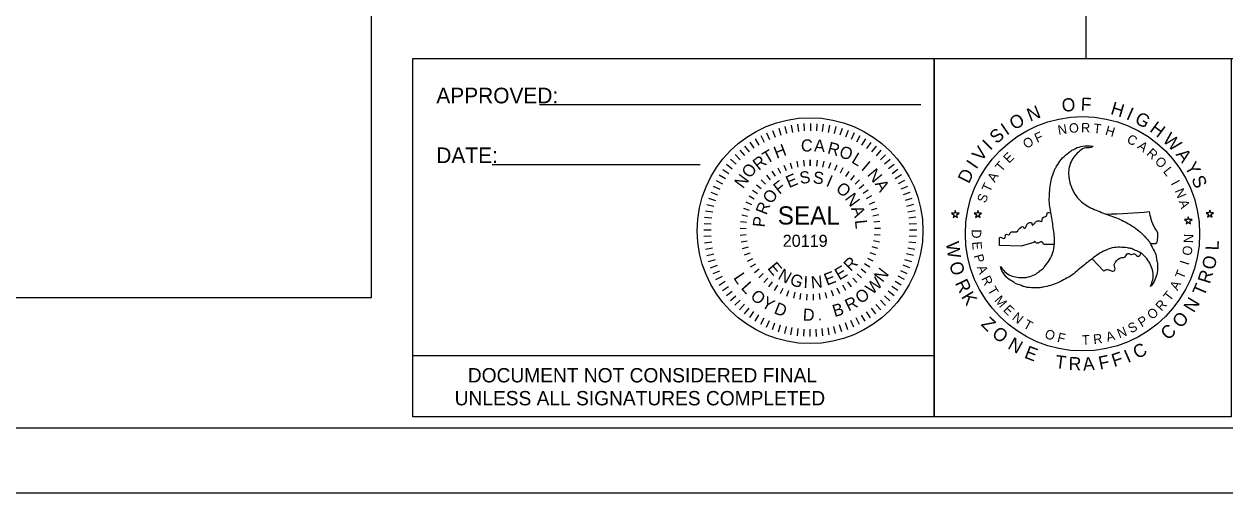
# Model space of a CAD drawing. Extents: x 1615234 to 1620694, y 898143 to 902846.
# Drawn here: x 1618110 to 1619493, y 899546 to 900086 of the extents above; entities that cross this region are included whole.
import ezdxf

# ---------------------------------------------------------------- set-up
doc = ezdxf.new("R2010")
doc.units = 0
for name, color, linetype in [('Default', 7, 'Continuous'), ('DEV BORDER CELL', 7, 'Continuous'), ('DEV DOT SWIRL SEAL CELL', 7, 'Continuous'), ('Scratch_Level_0', 7, 'Continuous'), ('Sheet Plan CELL', 7, 'Continuous'), ('Sheet Plot Border Outside CELL', 7, 'Continuous'), ('Sheet Sticker Exception Certification CELL', 7, 'Continuous'), ('Text', 7, 'Continuous')]:
    doc.layers.add(name, color=color, linetype=linetype)

msp = doc.modelspace()

# ---------------------------------------------------------------- linework, layer by layer
at = {"layer": 'Default'}
for p, q in [((1618971.7, 899963.7), (1618974.6, 899955.8)), ((1618978.7, 899966.1), (1618981.1, 899958.1)), ((1618985.8, 899968), (1618987.8, 899959.9)), ((1618993.1, 899969.6), (1618994.6, 899961.4)), ((1619000.4, 899970.7), (1619001.4, 899962.4)), ((1619007.8, 899971.4), (1619008.2, 899963)), ((1619015.2, 899971.6), (1619015.2, 899963.2)), ((1619022.6, 899971.3), (1619022.1, 899963)), ((1619029.9, 899970.7), (1619028.9, 899962.4)), ((1619037.3, 899969.6), (1619035.8, 899961.3)), ((1619044.5, 899968), (1619042.5, 899959.9)), ((1619051.6, 899966), (1619049.2, 899958)), ((1619058.6, 899963.6), (1619055.7, 899955.8)), ((1618945.5, 899949.9), (1618950.2, 899943.1)), ((1618951.7, 899953.9), (1618956, 899946.8)), ((1618958.2, 899957.6), (1618962, 899950.2)), ((1618964.8, 899960.8), (1618968.2, 899953.2)), ((1619065.5, 899960.7), (1619062, 899953.1)), ((1619072.1, 899957.5), (1619068.2, 899950.1)), ((1619078.6, 899953.8), (1619074.2, 899946.7)), ((1619084.8, 899949.8), (1619080, 899942.9)), ((1618928.4, 899935.7), (1618934.3, 899929.8)), ((1618933.8, 899940.8), (1618939.4, 899934.6)), ((1618939.5, 899945.6), (1618944.7, 899939)), ((1619090.8, 899945.4), (1619085.6, 899938.8)), ((1619096.5, 899940.7), (1619090.9, 899934.4)), ((1619101.8, 899935.6), (1619095.9, 899929.7)), ((1618918.6, 899924.7), (1618925.2, 899919.5)), ((1618923.3, 899930.4), (1618929.6, 899924.8)), ((1618977.6, 899920.5), (1618980.8, 899914.4)), ((1618984.6, 899923.8), (1618987.3, 899917.4)), ((1618992, 899926.4), (1618994, 899919.7)), ((1618999.6, 899928.3), (1619000.9, 899921.4)), ((1619007.3, 899929.4), (1619008, 899922.5)), ((1619015.1, 899929.8), (1619015.1, 899922.8)), ((1619015.1, 899922.8), (1619015.1, 899929.8)), ((1619022.9, 899929.4), (1619022.2, 899922.5)), ((1619030.6, 899928.2), (1619029.3, 899921.4)), ((1619038.2, 899926.4), (1619036.2, 899919.7)), ((1619045.6, 899923.8), (1619043, 899917.3)), ((1619052.7, 899920.5), (1619049.4, 899914.3)), ((1619106.9, 899930.2), (1619100.6, 899924.6)), ((1619111.6, 899924.5), (1619105.1, 899919.3)), ((1618910.2, 899912.5), (1618917.3, 899908.2)), ((1618914.2, 899918.7), (1618921.1, 899913.9)), ((1618958.6, 899906.8), (1618963.5, 899901.8)), ((1618964.5, 899912), (1618968.9, 899906.6)), ((1618970.8, 899916.6), (1618974.6, 899910.8)), ((1619059.4, 899916.5), (1619055.6, 899910.7)), ((1619065.7, 899911.9), (1619061.3, 899906.5)), ((1619071.6, 899906.7), (1619066.7, 899901.7)), ((1619116, 899918.5), (1619109.2, 899913.8)), ((1619120, 899912.3), (1619112.9, 899908)), ((1618903.3, 899899.4), (1618910.9, 899895.9)), ((1618906.5, 899906), (1618913.9, 899902.1)), ((1618948.6, 899894.9), (1618954.3, 899891)), ((1618953.3, 899901.1), (1618958.6, 899896.6)), ((1619076.9, 899901), (1619071.5, 899896.5)), ((1619081.6, 899894.8), (1619075.9, 899890.8)), ((1619123.7, 899905.8), (1619116.3, 899902)), ((1619126.9, 899899.2), (1619119.3, 899895.8)), ((1618898, 899885.5), (1618906, 899883.1)), ((1618900.4, 899892.5), (1618908.2, 899889.6)), ((1618941, 899881.3), (1618947.4, 899878.5)), ((1618944.5, 899888.3), (1618950.5, 899884.9)), ((1619085.7, 899888.2), (1619079.6, 899884.8)), ((1619089.2, 899881.2), (1619082.8, 899878.4)), ((1619129.8, 899892.3), (1619121.9, 899889.4)), ((1619132.2, 899885.3), (1619124.2, 899882.9)), ((1618894.4, 899871.2), (1618902.7, 899869.7)), ((1618896, 899878.4), (1618904.1, 899876.4)), ((1618936.1, 899866.5), (1618942.9, 899865)), ((1618938.2, 899874), (1618944.8, 899871.8)), ((1619091.9, 899873.8), (1619085.3, 899871.7)), ((1619094, 899866.3), (1619087.2, 899864.8)), ((1619134.1, 899878.2), (1619126, 899876.2)), ((1619135.7, 899870.9), (1619127.5, 899869.4)), ((1618892.7, 899856.5), (1618901, 899856)), ((1618893.3, 899863.8), (1618901.6, 899862.8)), ((1618934.8, 899858.8), (1618941.7, 899857.9)), ((1619095.3, 899858.6), (1619088.4, 899857.8)), ((1619136.8, 899863.6), (1619128.5, 899862.6)), ((1619137.5, 899856.2), (1619129.1, 899855.8)), ((1618892.4, 899849.1), (1618900.8, 899849.1)), ((1618892.6, 899841.7), (1618901, 899842.1)), ((1618934.2, 899851), (1618941.2, 899850.8)), ((1618934.4, 899843.2), (1618941.4, 899843.7)), ((1619095.7, 899843), (1619088.7, 899843.5)), ((1619095.9, 899850.8), (1619088.9, 899850.7)), ((1619137.4, 899841.4), (1619129.1, 899841.9)), ((1619137.7, 899848.8), (1619129.3, 899848.8)), ((1618893.3, 899834.3), (1618901.6, 899835.3)), ((1618894.4, 899827), (1618902.6, 899828.5)), ((1618935.4, 899835.4), (1618942.2, 899836.6)), ((1618937, 899827.8), (1618943.8, 899829.6)), ((1619093, 899827.6), (1619086.3, 899829.5)), ((1619087.9, 899836.7), (1619094.7, 899835.5)), ((1619135.6, 899826.7), (1619127.4, 899828.2)), ((1619136.8, 899834.1), (1619128.5, 899835.1)), ((1618896, 899819.7), (1618904.1, 899821.7)), ((1618897.9, 899812.6), (1618905.9, 899815)), ((1618939.5, 899820.4), (1618946, 899822.8)), ((1618942.6, 899813.2), (1618948.8, 899816.3)), ((1618946.3, 899806.4), (1618952.3, 899810)), ((1619083.7, 899806.2), (1619077.7, 899809.9)), ((1619087.5, 899813.1), (1619081.2, 899816.2)), ((1619090.6, 899820.2), (1619084.1, 899822.7)), ((1619132.1, 899812.4), (1619124.1, 899814.8)), ((1619134.1, 899819.5), (1619126, 899821.5)), ((1618900.3, 899805.6), (1618908.2, 899808.5)), ((1618903.2, 899798.7), (1618910.8, 899802.1)), ((1618906.4, 899792.1), (1618913.8, 899795.9)), ((1618950.8, 899799.9), (1618956.3, 899804.2)), ((1618955.8, 899794), (1618960.9, 899798.7)), ((1619074.2, 899793.9), (1619069.1, 899798.6)), ((1619079.2, 899799.8), (1619073.7, 899804)), ((1619126.8, 899798.5), (1619119.2, 899802)), ((1619129.7, 899805.4), (1619121.9, 899808.3)), ((1618910, 899785.6), (1618917.2, 899789.9)), ((1618914.1, 899779.4), (1618920.9, 899784.1)), ((1618961.4, 899788.5), (1618966, 899793.7)), ((1618967.5, 899783.6), (1618971.6, 899789.2)), ((1618974, 899779.3), (1618977.6, 899785.3)), ((1618980.9, 899775.7), (1618983.9, 899782)), ((1619049, 899775.6), (1619046.1, 899782)), ((1619056, 899779.2), (1619052.4, 899785.3)), ((1619062.5, 899783.5), (1619058.4, 899789.2)), ((1619068.6, 899788.4), (1619064, 899793.6)), ((1619115.9, 899779.2), (1619109, 899783.9)), ((1619119.9, 899785.4), (1619112.8, 899789.7)), ((1619123.6, 899791.9), (1619116.2, 899795.8)), ((1618918.4, 899773.4), (1618925, 899778.6)), ((1618923.2, 899767.7), (1618929.4, 899773.3)), ((1618928.3, 899762.3), (1618934.2, 899768.2)), ((1618988.2, 899772.7), (1618990.5, 899779.3)), ((1618997.3, 899777.3), (1618995.6, 899770.5)), ((1619003.3, 899769), (1619004.3, 899775.9)), ((1619011.1, 899768.2), (1619011.4, 899775.2)), ((1619018.9, 899768.2), (1619018.6, 899775.2)), ((1619026.6, 899769), (1619025.7, 899775.9)), ((1619034.3, 899770.5), (1619032.6, 899777.2)), ((1619041.8, 899772.7), (1619039.5, 899779.3)), ((1619106.8, 899767.5), (1619100.5, 899773.1)), ((1619111.5, 899773.2), (1619104.9, 899778.4)), ((1618933.6, 899757.2), (1618939.2, 899763.5)), ((1618939.3, 899752.5), (1618944.5, 899759.1)), ((1618945.3, 899748.1), (1618950, 899755)), ((1619084.6, 899748), (1619079.9, 899754.8)), ((1619090.6, 899752.3), (1619085.4, 899758.9)), ((1619096.3, 899757.1), (1619090.7, 899763.3)), ((1619101.7, 899762.2), (1619095.8, 899768.1)), ((1618951.5, 899744.1), (1618955.8, 899751.2)), ((1618958, 899740.4), (1618961.9, 899747.8)), ((1618964.6, 899737.2), (1618968, 899744.8)), ((1618971.5, 899734.3), (1618974.4, 899742.1)), ((1619058.4, 899734.2), (1619055.5, 899742.1)), ((1619065.3, 899737.1), (1619061.9, 899744.7)), ((1619071.9, 899740.3), (1619068.1, 899747.7)), ((1619078.4, 899743.9), (1619074.1, 899751.1)), ((1618978.5, 899731.9), (1618980.9, 899739.9)), ((1618985.6, 899729.9), (1618987.6, 899738)), ((1618992.8, 899728.3), (1618994.3, 899736.6)), ((1619000.2, 899727.2), (1619001.2, 899735.5)), ((1619007.5, 899726.6), (1619008, 899734.9)), ((1619014.9, 899726.3), (1619014.9, 899734.7)), ((1619022.3, 899726.5), (1619021.8, 899734.9)), ((1619029.7, 899727.2), (1619028.7, 899735.5)), ((1619037, 899728.3), (1619035.5, 899736.5)), ((1619044.3, 899729.9), (1619042.3, 899738)), ((1619051.4, 899731.8), (1619048.9, 899739.8))]:
    msp.add_line(p, q, dxfattribs=at)
at = {"layer": 'DEV BORDER CELL'}
for p, q in [((1618703.2, 899993.5), (1619142.2, 899993.5)), ((1619157.6, 899976), (1619157.6, 899634)), ((1618648.8, 899924.2), (1618888.2, 899924.2))]:
    msp.add_line(p, q, dxfattribs=at)
for points in [[(1620223.1, 902771.2), (1615723.1, 902771.2), (1615723.1, 899621.2), (1620223.1, 899621.2)], [(1618557.5, 900046.5), (1619157.6, 900046.5), (1619157.6, 899634), (1618557.5, 899634)], [(1619157.6, 900046.5), (1619499.6, 900046.5), (1619499.6, 899634), (1619157.6, 899634)]]:
    msp.add_lwpolyline(points, close=True, dxfattribs=at)
msp.add_circle((1619014.8, 899848.2), 130, dxfattribs=at)
at = {"layer": 'DEV DOT SWIRL SEAL CELL'}
for p, q in [((1619177.8, 899868.5), (1619180.5, 899866.6)), ((1619181.1, 899868.5), (1619177.8, 899868.5)), ((1619180.5, 899866.6), (1619179.5, 899863.4)), ((1619179.5, 899863.4), (1619182, 899865.4)), ((1619182, 899871.5), (1619181.1, 899868.5)), ((1619183.1, 899868.5), (1619182, 899871.5)), ((1619182, 899865.4), (1619184.7, 899863.4)), ((1619182, 899865.4), (1619184.7, 899863.4)), ((1619186.4, 899868.5), (1619183.1, 899868.5)), ((1619183.7, 899866.6), (1619186.4, 899868.5)), ((1619183.7, 899866.6), (1619186.4, 899868.5)), ((1619184.7, 899863.4), (1619183.7, 899866.6)), ((1619184.7, 899863.4), (1619183.7, 899866.6)), ((1619207.1, 899868.5), (1619203.8, 899868.5)), ((1619203.8, 899868.5), (1619206.5, 899866.5)), ((1619206.5, 899866.5), (1619205.5, 899863.4)), ((1619205.5, 899863.4), (1619208.1, 899865.3)), ((1619208.1, 899871.5), (1619207.1, 899868.5)), ((1619209.1, 899868.5), (1619208.1, 899871.5)), ((1619208.1, 899865.3), (1619210.7, 899863.4)), ((1619212.4, 899868.5), (1619209.1, 899868.5)), ((1619209.7, 899866.5), (1619212.4, 899868.5)), ((1619210.7, 899863.4), (1619209.7, 899866.5)), ((1619474.2, 899868.9), (1619471, 899868.9)), ((1619471, 899868.9), (1619473.6, 899867)), ((1619473.6, 899867), (1619472.7, 899863.9)), ((1619472.7, 899863.9), (1619475.2, 899865.8)), ((1619475.2, 899871.9), (1619474.2, 899868.9)), ((1619476.3, 899868.9), (1619475.2, 899871.9)), ((1619475.2, 899865.8), (1619477.8, 899863.9)), ((1619479.5, 899868.9), (1619476.3, 899868.9)), ((1619476.9, 899867), (1619479.5, 899868.9)), ((1619477.8, 899863.9), (1619476.9, 899867)), ((1619449.4, 899861), (1619446.1, 899861)), ((1619446.1, 899861), (1619448.8, 899859.1)), ((1619448.8, 899859.1), (1619447.8, 899855.9)), ((1619447.8, 899855.9), (1619450.4, 899857.9)), ((1619450.4, 899864), (1619449.4, 899861)), ((1619451.4, 899861), (1619450.4, 899864)), ((1619450.4, 899857.9), (1619453, 899855.9)), ((1619454.7, 899861), (1619451.4, 899861)), ((1619452, 899859.1), (1619454.7, 899861)), ((1619453, 899855.9), (1619452, 899859.1)), ((1619232.8, 899831.2), (1619233, 899839.1)), ((1619258, 899830.2), (1619232.8, 899831.2)), ((1619272.4, 899834.5), (1619258, 899830.2)), ((1619283.5, 899832.8), (1619296.1, 899832.7)), ((1619339.7, 899815.9), (1619352.6, 899801.9))]:
    msp.add_line(p, q, dxfattribs=at)
for start, end in [(265.6785, 265.9762), (271.2035, 275.3236)]:
    msp.add_arc((1619340.9, 900566.7), 699.6, start, end, dxfattribs=at)
for points in [[(1619234, 899806.8), (1619239.3, 899800.8), (1619245.8, 899796.6), (1619253.3, 899794.7), (1619261.7, 899794.2), (1619270.3, 899796.2), (1619276.1, 899799.1), (1619278.5, 899801), (1619282.7, 899804.3), (1619285.6, 899807.6), (1619290.6, 899814.6), (1619294.5, 899823), (1619296.1, 899832.6), (1619296.2, 899833.4), (1619296.1, 899842.4), (1619294.9, 899851.5), (1619293.6, 899860.3), (1619292, 899869.4), (1619290.6, 899878.4), (1619290.4, 899887.2), (1619291, 899897.3), (1619292.4, 899905.9), (1619295.2, 899914.8), (1619296.8, 899918.9), (1619298.8, 899922.3), (1619304.1, 899930.3), (1619310.9, 899936.7), (1619315.4, 899940.1), (1619319.7, 899942.4), (1619320.4, 899942.8), (1619329, 899945.5), (1619337.3, 899945.8), (1619340.2, 899945.1)], [(1619340.4, 899945.4), (1619340.2, 899945.1), (1619332.4, 899943.7), (1619325.4, 899940), (1619320, 899934.6), (1619315.4, 899927.6), (1619312.9, 899919), (1619312.5, 899912.7), (1619313, 899909.6), (1619313.8, 899904.3), (1619315, 899900.1), (1619318.7, 899892.3), (1619324, 899884.7), (1619331.5, 899878.5), (1619332.2, 899878), (1619339.9, 899873.6), (1619348.5, 899870.1), (1619356.8, 899866.8), (1619365.4, 899863.7), (1619373.9, 899860.3), (1619381.6, 899856.1), (1619390.1, 899850.6), (1619396.8, 899845.1), (1619403.1, 899838.3), (1619406, 899834.8), (1619407.8, 899831.2), (1619412.2, 899822.8), (1619414.3, 899813.6), (1619415, 899808), (1619414.8, 899803.1), (1619414.8, 899802.3), (1619412.8, 899793.6), (1619408.9, 899786.1), (1619406.9, 899784.1)], [(1619233, 899839.1), (1619232.8, 899839.9), (1619234.1, 899840.7), (1619237.9, 899839.2), (1619239.7, 899840.8), (1619239.7, 899842.4), (1619241.2, 899844.1), (1619243.7, 899843.5), (1619246, 899846.4), (1619248.1, 899847), (1619252.6, 899847), (1619258, 899852.4), (1619260.2, 899852.7), (1619260.8, 899851.3), (1619262.1, 899851), (1619264.5, 899855.4), (1619265.1, 899856), (1619269.1, 899857.7), (1619270.3, 899856.9), (1619270.6, 899854.9), (1619271.2, 899854.6), (1619272.5, 899855.5), (1619274.4, 899857.9), (1619277.8, 899859.7), (1619281.7, 899859.1), (1619282.4, 899862.4), (1619287, 899865.4), (1619287.9, 899867.3), (1619288.1, 899869.2)], [(1619406.7, 899833.5), (1619414.1, 899834.4), (1619415.2, 899840.2), (1619415.3, 899845.2), (1619412.2, 899850.8), (1619407.7, 899861.3), (1619405.8, 899870.2)], [(1619406.9, 899784.1), (1619409.5, 899791.5), (1619409.9, 899799.4), (1619407.8, 899806.8), (1619404, 899814.3), (1619398, 899820.8), (1619392.7, 899824.3), (1619389.7, 899825.4), (1619384.9, 899827.5), (1619380.4, 899828.4), (1619371.9, 899829.1), (1619362.6, 899828.3), (1619353.5, 899824.9), (1619352.8, 899824.6), (1619345.1, 899820), (1619337.7, 899814.4), (1619330.7, 899808.9), (1619323.7, 899803), (1619316.6, 899797.2), (1619309.1, 899792.7), (1619300.1, 899788.1), (1619291.9, 899785.1), (1619282.9, 899783.1), (1619278.4, 899782.3), (1619274.4, 899782.4), (1619265, 899782.9), (1619255.9, 899785.7), (1619250.8, 899787.8), (1619246.7, 899790.5), (1619245.9, 899790.9), (1619239.3, 899796.9), (1619234.9, 899804), (1619234, 899806.8)], [(1619283.5, 899832.8), (1619282.5, 899834.7), (1619280.4, 899835.3), (1619277.6, 899833.9), (1619275.6, 899834), (1619273.3, 899835.7), (1619272.4, 899834.5)], [(1619352.6, 899801.9), (1619357.7, 899803.4), (1619362, 899801.8), (1619364, 899801.5), (1619365.7, 899802.8), (1619365.2, 899809.1), (1619366.6, 899812.1), (1619373.5, 899817.2), (1619377.7, 899818.1), (1619380.9, 899822), (1619382.2, 899821.9), (1619384.1, 899820.8), (1619388.4, 899821.7), (1619391.9, 899818.9), (1619393.9, 899819), (1619395.6, 899822.2)]]:
    msp.add_spline(points, degree=3, dxfattribs=at)
at = {"layer": 'Scratch_Level_0'}
msp.add_lwpolyline([(1620073.1, 902621.2), (1615873.1, 902621.2), (1615873.1, 899771.2), (1618509.6, 899771.2), (1618509.6, 900126), (1620073.1, 900126)], close=True, dxfattribs=at)
at = {"layer": 'Sheet Plan CELL'}
msp.add_lwpolyline([(1620207.6, 900189.1), (1619332.6, 900189.1), (1619332.6, 900046.5), (1620207.6, 900046.5)], close=True, dxfattribs=at)
at = {"layer": 'Sheet Plot Border Outside CELL'}
msp.add_lwpolyline([(1615234.1, 899546.2), (1620298.1, 899546.2), (1620298.1, 902846.2), (1615234.1, 902846.2)], close=True, dxfattribs=at)
at = {"layer": 'Sheet Sticker Exception Certification CELL'}
for p, q in [((1618557.5, 899634), (1618557.5, 899704.5)), ((1618557.5, 899704.5), (1619157.6, 899704.5)), ((1619157.6, 899704.5), (1619157.6, 899634)), ((1619157.6, 899634), (1618557.5, 899634))]:
    msp.add_line(p, q, dxfattribs=at)
at = {"layer": 'Text'}
msp.add_circle((1619328.6, 899844.6), 134.9, dxfattribs=at)

# ---------------------------------------------------------------- texts
at = {"layer": 'Default'}
for s, height, rotation, p in [('H', 13.9, 21.0146, (1618976.3, 899930.8)), ('C', 13.9, 357.3039, (1619004, 899939.7)), ('A', 13.9, 357.3039, (1619019.2, 899939.4)), ('R', 13.9, 345.2946, (1619034, 899937.3)), ('T', 13.9, 30.4466, (1618965.1, 899924.7)), ('O', 13.9, 342.2378, (1619047.4, 899933.3)), ('L', 13.9, 329.1015, (1619061.6, 899927.1)), ('O', 13.9, 51.6643, (1618945.6, 899907.6)), ('R', 13.9, 38.6075, (1618955.7, 899916.9)), ('I', 13.9, 319.5261, (1619072.8, 899919)), ('N', 13.9, 53.6237, (1618937.6, 899895.8)), ('F', 13.9, 38.1876, (1618979.4, 899889.3)), ('E', 13.9, 22.8914, (1618990.5, 899897.1)), ('S', 13.9, 7.5951, (1619003.6, 899901.9)), ('S', 13.9, 352.2989, (1619017.5, 899903)), ('I', 13.9, 337.0026, (1619032.3, 899900)), ('N', 13.9, 310.2316, (1619079.8, 899912.4)), ('O', 13.9, 53.4838, (1618970.1, 899878)), ('O', 13.9, 321.7064, (1619043.5, 899894.6)), ('A', 13.9, 300.4641, (1619089, 899902.1)), ('R', 13.9, 68.7801, (1618964.6, 899865.5)), ('N', 13.9, 306.4101, (1619054.2, 899885.2)), ('SEAL', 20.9, 359.947, (1618977.6, 899855.3)), ('A', 13.9, 291.1139, (1619061.9, 899873.8)), ('P', 13.9, 84.0763, (1618962.5, 899851.7)), ('L', 13.9, 275.8176, (1619066.4, 899860.1)), ('20119', 13.92, 359.947, (1618983.3, 899829.6)), ('E', 13.9, 310.0171, (1618965.1, 899804.8)), ('R', 13.9, 44.5119, (1619061.6, 899800.4)), ('L', 13.9, 303.882, (1618926, 899793.9)), ('N', 13.9, 330.8721, (1618976.8, 899793.2)), ('G', 13.9, 339.6384, (1618990.4, 899786.6)), ('I', 13.9, 357.7332, (1619007, 899782.2)), ('N', 13.9, 5.3628, (1619016.4, 899781.7)), ('E', 13.9, 20.7549, (1619034.1, 899784.8)), ('E', 13.9, 30.7408, (1619048.4, 899790.7)), ('W', 13.9, 43.2714, (1619086.6, 899773.8)), ('N', 13.9, 52.154, (1619098.3, 899787.8)), ('L', 13.9, 311.9538, (1618934.6, 899781.9)), ('O', 13.9, 320.5966, (1618945.1, 899771)), ('Y', 13.9, 329.2691, (1618957.8, 899761.3)), ('R', 13.9, 25.5662, (1619059.1, 899755.1)), ('O', 13.9, 34.3888, (1619072.9, 899763.4)), ('D', 13.9, 338.2416, (1618972.3, 899753.4)), ('D', 13.9, 356.0369, (1619006.1, 899744.9)), ('B', 13.9, 16.5636, (1619043, 899748.7)), ('.', 13.9, 3.7793, (1619023.7, 899744.7))]:
    msp.add_text(s, height=height, rotation=rotation, dxfattribs=at).set_placement(p)
at = {"layer": 'DEV BORDER CELL'}
for s, p in [('APPROVED:  ', (1618584.4, 899994.8)), ('DATE:  ', (1618584.4, 899926))]:
    msp.add_text(s, height=18, dxfattribs=at).set_placement(p)
at = {"layer": 'DEV DOT SWIRL SEAL CELL'}
for s, height, rotation, p in [('N', 15.1, 21.5861, (1619268.2, 899973.6)), ('O', 15.1, 5.7649, (1619305.4, 899984.8)), ('F', 15.1, 357.2575, (1619326.3, 899986.5)), ('H', 15.1, 343.454, (1619360, 899982.6)), ('I', 15.1, 335.804, (1619377.9, 899977)), ('O', 15.1, 30.0935, (1619249.9, 899963.5)), ('G', 15.1, 331.5167, (1619387.6, 899972.8)), ('S', 15.1, 40.5848, (1619229.6, 899947.5)), ('I', 15.1, 34.3808, (1619241.2, 899957.4)), ('F', 10.9, 24.2569, (1619276.3, 899949.1)), ('N', 10.9, 9.0227, (1619301, 899958.5)), ('O', 10.9, 3.9446, (1619313.4, 899960.6)), ('R', 10.9, 358.8665, (1619326.8, 899961.4)), ('H', 10.9, 343.6322, (1619354, 899958.9)), ('H', 15.1, 323.4632, (1619404.9, 899963.1)), ('W', 15.1, 315.8133, (1619419.9, 899951.7)), ('I', 15.1, 44.8722, (1619222.3, 899939.9)), ('O', 10.9, 29.335, (1619263.7, 899942.1)), ('C', 10.9, 333.4761, (1619378.7, 899950.1)), ('A', 10.9, 323.3199, (1619391, 899943.7)), ('V', 15.1, 51.5806, (1619211.9, 899927)), ('E', 10.9, 44.5692, (1619243.8, 899925)), ('R', 10.9, 318.2418, (1619401.5, 899936.1)), ('A', 15.1, 306.7762, (1619435.4, 899935.8)), ('I', 15.1, 55.8679, (1619206.2, 899918.2)), ('T', 10.9, 49.6473, (1619235.3, 899915.1)), ('O', 10.9, 313.1637, (1619411.1, 899927.3)), ('L', 10.9, 308.0856, (1619420.8, 899916.3)), ('Y', 15.1, 299.7484, (1619445.7, 899921.9)), ('D', 15.1, 63.459, (1619197.6, 899901.6)), ('A', 10.9, 59.8035, (1619227.6, 899903.1)), ('I', 10.9, 297.9295, (1619429.9, 899902.8)), ('S', 15.1, 293.2249, (1619453.6, 899907.9)), ('T', 10.9, 64.8816, (1619221.8, 899891.7)), ('N', 10.9, 292.8514, (1619434.5, 899894.1)), ('S', 10.9, 69.9597, (1619217, 899879.3)), ('A', 10.9, 287.7733, (1619439.3, 899881.9)), ('D', 10.9, 270.272, (1619201, 899849.7)), ('N', 10.9, 87.733, (1619455.9, 899833.7)), ('E', 10.9, 275.3501, (1619201.3, 899835.2)), ('O', 10.9, 82.9269, (1619454.1, 899819)), ('P', 10.9, 285.5063, (1619203.1, 899819.5)), ('I', 10.9, 72.7707, (1619450.8, 899807.8)), ('A', 10.9, 290.5843, (1619206.7, 899806.2)), ('R', 10.9, 295.6624, (1619211.7, 899793.2)), ('T', 10.9, 67.6926, (1619444.8, 899791.6)), ('T', 10.9, 300.7405, (1619218.6, 899779.9)), ('A', 10.9, 62.6145, (1619438.1, 899778.6)), ('M', 10.9, 310.8967, (1619226.4, 899767.7)), ('R', 10.9, 47.3803, (1619419.5, 899754.9)), ('T', 10.9, 52.4584, (1619429.3, 899766.2)), ('E', 10.9, 315.9748, (1619236.5, 899756.2)), ('N', 10.9, 321.0529, (1619246.7, 899746.7)), ('O', 10.9, 42.3022, (1619408.9, 899745.1)), ('T', 10.9, 331.209, (1619259.4, 899737)), ('S', 10.9, 27.068, (1619384.3, 899729.8)), ('P', 10.9, 32.146, (1619396.7, 899736.7)), ('O', 10.9, 341.3652, (1619284.1, 899725)), ('F', 10.9, 346.4433, (1619298.8, 899720.5)), ('T', 10.9, 1.6775, (1619328.1, 899716.9)), ('R', 10.9, 6.7556, (1619341.6, 899717.6)), ('A', 10.9, 16.9118, (1619357.4, 899720)), ('N', 10.9, 21.9899, (1619371.1, 899724.1))]:
    msp.add_text(s, height=height, rotation=rotation, dxfattribs=at).set_placement(p)
at = {"layer": 'Sheet Sticker Exception Certification CELL'}
for s, p in [('DOCUMENT NOT CONSIDERED FINAL', (1618620.7, 899673.5)), ('UNLESS ALL SIGNATURES COMPLETED', (1618605.5, 899647.1))]:
    msp.add_text(s, height=16.5, dxfattribs=at).set_placement(p)
at = {"layer": 'Text'}
for s, height, rotation, p in [('T', 10.9, 353.7884, (1619340.7, 899960.8)), ('W', 15.1, 278.15, (1619171.2, 899834.5)), ('L', 15.1, 87.429, (1619485.2, 899825.3)), ('O', 15.1, 287.1147, (1619174.7, 899810.1)), ('O', 15.1, 78.9896, (1619480.7, 899802.5)), ('R', 15.1, 72.7519, (1619475.2, 899786.2)), ('R', 15.1, 295.5541, (1619181.4, 899787.9)), ('T', 15.1, 66.881, (1619468.5, 899771.6)), ('K', 15.1, 301.7918, (1619188.4, 899772.2)), ('N', 15.1, 58.892, (1619456.9, 899752.8)), ('Z', 15.1, 316.1688, (1619210.8, 899739.7)), ('O', 15.1, 50.4526, (1619442.1, 899735)), ('O', 15.1, 322.5233, (1619223.1, 899727.3)), ('C', 15.1, 43.0807, (1619427.1, 899721.3)), ('N', 15.1, 330.9626, (1619241.5, 899713.1)), ('E', 15.1, 338.9517, (1619260.6, 899702.2)), ('C', 15.1, 28.0033, (1619391.6, 899700)), ('T', 15.1, 352.6948, (1619296.4, 899690.2)), ('R', 15.1, 358.5656, (1619312.4, 899687.7)), ('A', 15.1, 4.8034, (1619329.5, 899686.9)), ('F', 15.1, 11.7751, (1619348.7, 899688.1)), ('F', 15.1, 17.7627, (1619364.9, 899691.1)), ('I', 15.1, 23.7503, (1619380.7, 899695.7))]:
    msp.add_text(s, height=height, rotation=rotation, dxfattribs=at).set_placement(p)

doc.saveas('drawing.dxf')
